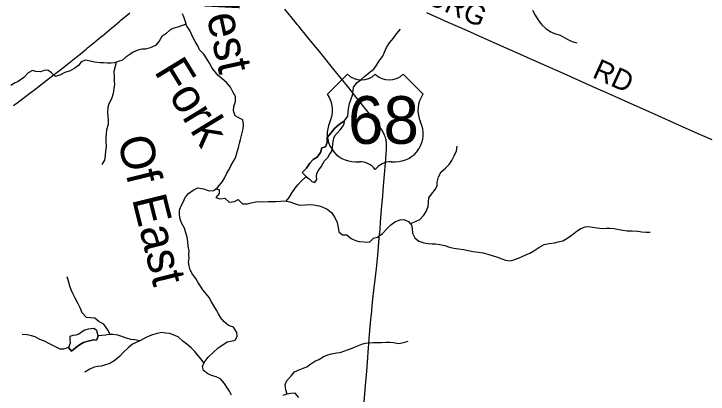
# Model space of a CAD drawing. Extents: x 1442749 to 1756758, y 235267 to 677782.
# Drawn here: x 1566168 to 1576295, y 462839 to 468390 of the extents above; entities that cross this region are included whole.
import ezdxf

# ---------------------------------------------------------------- set-up
doc = ezdxf.new("R2010")
doc.units = 0
for name, color, linetype in [('GM_X_County_Road', 7, 'Continuous'), ('GM_X_County_Road_Text', 7, 'Continuous'), ('GM_X_Minor_Lake', 7, 'Continuous'), ('GM_X_Minor_River', 7, 'Continuous'), ('GM_X_Minor_River_Text', 7, 'Continuous'), ('GM_X_US_Location', 7, 'Continuous'), ('GM_X_US_Route', 7, 'Continuous'), ('GM_X_US_Shield', 7, 'Continuous')]:
    doc.layers.add(name, color=color, linetype=linetype)

msp = doc.modelspace()

# ---------------------------------------------------------------- linework, layer by layer
at = {"layer": 'GM_X_County_Road'}
for points in [[(1566163, 467053), (1566237, 467107), (1566401, 467232), (1566493, 467303), (1566515, 467320), (1566655, 467428), (1566673, 467442), (1566798, 467539), (1566827, 467561), (1566929, 467641), (1566951, 467658), (1567069, 467751), (1567136, 467804), (1567223, 467876), (1567243, 467892), (1567314, 467951), (1567334, 467968), (1567438, 468053), (1567460, 468071), (1567598, 468185), (1567618, 468202), (1567709, 468280), (1567729, 468297), (1567859, 468406)], [(1572187, 468409), (1572496, 468271), (1572666, 468195), (1572822, 468126), (1572939, 468074), (1573224, 467946), (1573390, 467875), (1573857, 467666), (1574234, 467498), (1574608, 467329), (1574752, 467265), (1574971, 467169), (1575124, 467100), (1575508, 466930), (1575873, 466767), (1576146, 466646), (1576350, 466556)]]:
    msp.add_lwpolyline(points, dxfattribs=at)
at = {"layer": 'GM_X_Minor_Lake'}
for points in [[(1570989, 466830), (1570918, 466779), (1570849, 466722), (1570792, 466651), (1570739, 466585), (1570736, 466513), (1570713, 466449), (1570662, 466434), (1570639, 466366), (1570594, 466297), (1570534, 466263), (1570485, 466212), (1570434, 466138), (1570375, 466075), (1570432, 466014)], [(1570432, 466014), (1570474, 465982), (1570513, 465945), (1570557, 465930), (1570588, 465972), (1570584, 466016), (1570587, 466062), (1570616, 466112), (1570648, 466158), (1570673, 466201), (1570700, 466245), (1570747, 466293), (1570773, 466336), (1570806, 466386), (1570813, 466434), (1570819, 466486), (1570824, 466528), (1570833, 466574), (1570853, 466620), (1570884, 466648), (1570925, 466699), (1570959, 466743), (1570988, 466784), (1570989, 466830)], [(1567399, 463692), (1567378, 463761), (1567337, 463795), (1567295, 463792), (1567253, 463786), (1567202, 463773), (1567156, 463744), (1567113, 463714), (1567069, 463699), (1567029, 463697), (1566985, 463678), (1566982, 463632), (1566991, 463585), (1566963, 463520)], [(1566963, 463520), (1567008, 463467), (1567068, 463516), (1567127, 463559), (1567182, 463593), (1567248, 463612), (1567308, 463625), (1567378, 463630), (1567399, 463692)]]:
    msp.add_lwpolyline(points, dxfattribs=at)
at = {"layer": 'GM_X_Minor_River'}
for points in [[(1568999, 463133), (1568936, 463184), (1568920, 463240), (1568941, 463302), (1569004, 463376), (1569073, 463445), (1569147, 463514), (1569201, 463551), (1569280, 463602), (1569330, 463614), (1569398, 463625), (1569423, 463681), (1569418, 463739), (1569369, 463814), (1569299, 463843), (1569232, 463898), (1569187, 463952), (1569152, 464009), (1569122, 464064), (1569085, 464126), (1569052, 464185), (1569017, 464251), (1568974, 464302), (1568923, 464363), (1568889, 464416), (1568852, 464474), (1568821, 464527), (1568772, 464592), (1568741, 464654), (1568723, 464712), (1568716, 464765), (1568723, 464821), (1568722, 464877), (1568723, 464929), (1568712, 465001), (1568703, 465062), (1568694, 465132), (1568673, 465210), (1568657, 465263), (1568613, 465341), (1568595, 465394), (1568582, 465458), (1568585, 465524), (1568602, 465576), (1568635, 465640), (1568668, 465709), (1568713, 465769), (1568784, 465814), (1568852, 465851), (1568936, 465834), (1569014, 465809), (1569082, 465810), (1569145, 465861), (1569212, 465941), (1569241, 465994), (1569276, 466066), (1569307, 466118), (1569333, 466172), (1569366, 466231), (1569399, 466289), (1569426, 466375), (1569443, 466433), (1569460, 466501), (1569475, 466556), (1569494, 466634), (1569511, 466714), (1569518, 466770), (1569509, 466841), (1569450, 466872), (1569398, 466902), (1569373, 466977), (1569376, 467037), (1569401, 467109), (1569400, 467183), (1569361, 467252), (1569326, 467320), (1569271, 467389), (1569206, 467440), (1569150, 467491), (1569103, 467544), (1569062, 467598), (1569021, 467671), (1568982, 467734), (1568939, 467803), (1568873, 467866), (1568854, 467916), (1568811, 467989), (1568784, 468041), (1568759, 468096), (1568735, 468148), (1568684, 468221), (1568669, 468275), (1568650, 468334), (1568625, 468392)], [(1573731, 468445), (1573774, 468370), (1573813, 468309), (1573864, 468237), (1573933, 468172), (1574000, 468127), (1574056, 468106), (1574134, 468081), (1574205, 468040), (1574259, 468013), (1574313, 467988), (1574381, 467967)], [(1568680, 468238), (1568612, 468216), (1568560, 468195), (1568502, 468181), (1568445, 468158), (1568386, 468101), (1568328, 468060), (1568285, 467994), (1568232, 467929), (1568155, 467893), (1568087, 467876), (1568035, 467873), (1567976, 467862), (1567910, 467833), (1567859, 467797), (1567801, 467760), (1567750, 467715), (1567688, 467695), (1567635, 467676), (1567585, 467671), (1567533, 467671), (1567477, 467676), (1567427, 467675), (1567345, 467684), (1567279, 467701), (1567210, 467714), (1567147, 467689), (1567108, 467637), (1567056, 467598), (1566987, 467561), (1566913, 467532), (1566846, 467500), (1566776, 467477), (1566718, 467530), (1566665, 467567), (1566609, 467564), (1566556, 467544), (1566490, 467547), (1566439, 467562), (1566376, 467531), (1566311, 467462), (1566230, 467404), (1566176, 467377), (1566121, 467344)], [(1570141, 465654), (1570181, 465711), (1570227, 465784), (1570271, 465844), (1570312, 465896), (1570361, 465955), (1570432, 466014), (1570375, 466075), (1570434, 466138), (1570485, 466212), (1570534, 466263), (1570594, 466297), (1570639, 466366), (1570662, 466434), (1570713, 466449), (1570736, 466513), (1570739, 466585), (1570792, 466651), (1570849, 466722), (1570918, 466779), (1570989, 466830), (1571040, 466896), (1571046, 466950), (1571049, 467006), (1571062, 467080), (1571083, 467134), (1571108, 467204), (1571119, 467272), (1571124, 467322), (1571177, 467387), (1571231, 467427), (1571284, 467478), (1571363, 467545), (1571414, 467580), (1571453, 467632), (1571498, 467704), (1571549, 467775), (1571574, 467829), (1571601, 467897), (1571646, 467968), (1571703, 468036), (1571750, 468099), (1571805, 468166)], [(1567659, 467685), (1567643, 467622), (1567626, 467548), (1567631, 467482), (1567632, 467409), (1567633, 467359), (1567626, 467307), (1567617, 467229), (1567590, 467151), (1567551, 467078), (1567540, 467026), (1567531, 466952), (1567538, 466894), (1567545, 466837), (1567542, 466773), (1567519, 466697), (1567512, 466637), (1567509, 466583), (1567511, 466527), (1567512, 466453), (1567505, 466389), (1567500, 466321), (1567491, 466253), (1567450, 466191)], [(1571951, 465328), (1572024, 465357), (1572089, 465390), (1572146, 465452), (1572181, 465507), (1572210, 465579), (1572215, 465641), (1572223, 465703), (1572258, 465759), (1572313, 465828), (1572340, 465882), (1572343, 465934), (1572360, 466010), (1572399, 466084), (1572464, 466137), (1572515, 466190), (1572558, 466250), (1572591, 466318), (1572622, 466389), (1572633, 466457)], [(1569112, 465835), (1569160, 465825), (1569161, 465767), (1569116, 465711), (1569172, 465689), (1569244, 465698), (1569308, 465639), (1569384, 465650), (1569440, 465681), (1569501, 465618), (1569576, 465617), (1569628, 465632), (1569696, 465647), (1569752, 465651), (1569808, 465646), (1569876, 465651), (1569926, 465652), (1569996, 465653), (1570061, 465658), (1570113, 465660), (1570193, 465645), (1570274, 465619), (1570332, 465599), (1570418, 465601), (1570480, 465605), (1570536, 465604), (1570622, 465587), (1570674, 465568), (1570736, 465537), (1570803, 465490), (1570848, 465419), (1570885, 465344), (1570900, 465272), (1570909, 465206), (1570962, 465163), (1571026, 465166), (1571088, 465113), (1571149, 465082), (1571203, 465068), (1571277, 465060), (1571353, 465055), (1571414, 465115), (1571472, 465128), (1571545, 465183), (1571614, 465256), (1571665, 465310), (1571724, 465355), (1571804, 465382), (1571858, 465387), (1571924, 465360), (1571969, 465306), (1571979, 465255), (1571984, 465187), (1572015, 465119), (1572074, 465072), (1572148, 465047), (1572212, 465038), (1572270, 465035), (1572320, 465032), (1572382, 465023), (1572454, 465008), (1572523, 464985), (1572583, 464971), (1572653, 464960), (1572725, 464951), (1572793, 464934), (1572867, 464923), (1572941, 464910), (1573013, 464901), (1573082, 464884), (1573160, 464860), (1573220, 464838), (1573286, 464813), (1573337, 464796), (1573403, 464787), (1573460, 464800), (1573528, 464825), (1573582, 464849), (1573637, 464874), (1573695, 464899), (1573750, 464933), (1573825, 464980), (1573903, 465025), (1573974, 465038), (1574054, 465047), (1574108, 465062), (1574176, 465079), (1574233, 465112), (1574283, 465144), (1574334, 465183), (1574385, 465225), (1574437, 465258), (1574502, 465283), (1574552, 465284), (1574614, 465276), (1574678, 465267), (1574754, 465258), (1574808, 465261), (1574864, 465264), (1574924, 465257), (1574994, 465244)], [(1574994, 465244), (1575051, 465230), (1575115, 465223), (1575187, 465224), (1575269, 465219), (1575327, 465210), (1575393, 465203), (1575447, 465204)], [(1567570, 463709), (1567533, 463780), (1567482, 463859), (1567414, 463894), (1567347, 463949), (1567287, 463954), (1567229, 463957), (1567164, 464024), (1567139, 464087), (1567100, 464165), (1567061, 464242), (1567032, 464296), (1567005, 464361), (1566985, 464413), (1566962, 464490), (1566947, 464552)], [(1568006, 463619), (1567931, 463629), (1567879, 463637), (1567805, 463656), (1567740, 463681), (1567684, 463700), (1567612, 463711), (1567556, 463708), (1567504, 463699), (1567399, 463692), (1567378, 463630), (1567308, 463625), (1567248, 463612), (1567182, 463593), (1567127, 463559), (1567068, 463516), (1567008, 463467), (1566963, 463520), (1566892, 463493), (1566842, 463495), (1566754, 463538), (1566687, 463571), (1566615, 463611), (1566546, 463638), (1566476, 463675), (1566424, 463691), (1566360, 463702), (1566290, 463709)], [(1568940, 463297), (1568902, 463347), (1568847, 463410), (1568805, 463460), (1568752, 463515), (1568691, 463566), (1568639, 463609), (1568562, 463676), (1568503, 463701), (1568441, 463722), (1568381, 463731), (1568327, 463736), (1568259, 463722), (1568190, 463703), (1568126, 463678), (1568067, 463649), (1568003, 463618), (1567952, 463594), (1567898, 463567), (1567833, 463514), (1567760, 463445), (1567709, 463387), (1567646, 463336), (1567566, 463285), (1567505, 463264), (1567443, 463248), (1567391, 463243), (1567339, 463230), (1567276, 463205), (1567201, 463158)], [(1570156, 462840), (1570137, 462901), (1570126, 462973), (1570144, 463027), (1570216, 463110), (1570261, 463162), (1570339, 463197), (1570389, 463216), (1570442, 463238), (1570500, 463281), (1570559, 463318), (1570614, 463346), (1570680, 463385), (1570747, 463414), (1570801, 463429), (1570875, 463442), (1570925, 463448), (1570980, 463465), (1571034, 463484), (1571100, 463511), (1571169, 463538), (1571241, 463566), (1571294, 463581), (1571356, 463588), (1571408, 463593), (1571478, 463592), (1571532, 463594), (1571600, 463597), (1571650, 463598), (1571704, 463591), (1571782, 463576), (1571852, 463591), (1571919, 463610)], [(1569341, 462822), (1569313, 462882), (1569274, 462939), (1569241, 462995), (1569182, 463062), (1569118, 463093), (1569051, 463112), (1568999, 463133)], [(1570323, 462790), (1570272, 462855), (1570206, 462850), (1570150, 462839), (1570089, 462817)]]:
    msp.add_lwpolyline(points, dxfattribs=at)
at = {"layer": 'GM_X_US_Route'}
msp.add_lwpolyline([(1571259, 462494), (1571298, 462963), (1571314, 463173), (1571330, 463367), (1571337, 463455), (1571341, 463508), (1571346, 463576), (1571352, 463652), (1571371, 463879), (1571379, 463966), (1571388, 464050), (1571396, 464132), (1571411, 464276), (1571419, 464346), (1571425, 464399), (1571433, 464469), (1571446, 464588), (1571455, 464671), (1571475, 464864), (1571498, 465119), (1571509, 465243), (1571518, 465348), (1571532, 465537), (1571548, 465727), (1571555, 465815), (1571573, 466044), (1571589, 466211), (1571598, 466345), (1571603, 466415), (1571604, 466445), (1571604, 466462), (1571604, 466477), (1571603, 466497), (1571601, 466511), (1571599, 466528), (1571596, 466550), (1571593, 466564), (1571590, 466575), (1571588, 466582), (1571583, 466600), (1571576, 466617), (1571569, 466635), (1571561, 466650), (1571554, 466665), (1571550, 466672), (1571541, 466686), (1571536, 466694), (1571531, 466703), (1571524, 466712), (1571511, 466730), (1571500, 466746), (1571483, 466769), (1571470, 466786), (1571464, 466794), (1571450, 466811), (1571118, 467230), (1571057, 467304), (1570837, 467578), (1570643, 467817), (1570456, 468046), (1570435, 468071), (1570396, 468119), (1570374, 468147), (1570322, 468211), (1570306, 468231), (1570272, 468273), (1570119, 468461)], dxfattribs=at)
at = {"layer": 'GM_X_US_Shield'}
for p, q in [((1571034, 467508), (1570743, 467218)), ((1572136, 467218), (1571846, 467508)), ((1571150, 466232), (1571208, 466232)), ((1571672, 466232), (1571730, 466232))]:
    msp.add_line(p, q, dxfattribs=at)
for centre, radius, start, end in [((1571237, 467715), 290, 225.573, 314.427), ((1571643, 467715), 290, 225.573, 314.427), ((1570411, 466985), 406, 334.5471, 35.0009), ((1572468, 466985), 406, 144.9991, 205.4529), ((1571145, 466638), 406, 154.8319, 270.6383), ((1571734, 466638), 406, 269.3617, 25.1681), ((1571208, 465942), 290, 36.8699, 90), ((1571672, 465942), 290, 90, 143.1301)]:
    msp.add_arc(centre, radius, start, end, dxfattribs=at)

# ---------------------------------------------------------------- texts
at = {"layer": 'GM_X_County_Road_Text'}
for s, rotation, p in [('LYNCHBURG', 335.9252, (1570679, 469216)), ('RD', 335.6367, (1574591, 467469))]:
    msp.add_text(s, height=300, rotation=rotation, dxfattribs=at).set_placement(p)
at = {"layer": 'GM_X_Minor_River_Text'}
for s, rotation, p in [('West', 282.3346, (1568842, 468980)), ('Fork', 301.4492, (1568205, 467551)), ('Of East', 283.869, (1567675, 466555))]:
    msp.add_text(s, height=500, rotation=rotation, dxfattribs=at).set_placement(p)
at = {"layer": 'GM_X_US_Location'}
for s in ['0', '/']:
    msp.add_text(s, height=1, dxfattribs=at).set_placement((1571439, 466836))
msp.add_text('68', height=1, rotation=0, dxfattribs=at).set_placement((1571233, 466629))
at = {"layer": 'GM_X_US_Shield'}
msp.add_text('68', height=696.1, dxfattribs=at).set_placement((1571041, 466493))

doc.saveas('drawing.dxf')
